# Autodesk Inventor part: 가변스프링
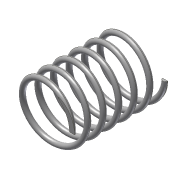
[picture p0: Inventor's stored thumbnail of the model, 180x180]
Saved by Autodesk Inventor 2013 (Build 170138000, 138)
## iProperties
Created: 2018-06
Part Number: 가변스프링
Material: 강철, 연강
Document SubType Name: Modeling
Designer: Administrator
Density: 7.86 g/cm^3
Mass: 82.8002 g
Surface Area: 106.473 cm^2
Volume: 10.5344 cm^3
Author: Administrator
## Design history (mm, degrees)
sketch "스케치1"
  geometry: L1 (0, 0)-(0, 73.25); L2 (0, 73.25)-(22.5, 73.25); C1 r 2 at (22.5, 0)
  constraints: 4 end point, 1 centre point, 1 horizontal alignment, 1 perpendicular, 1 vertical, 1 vertical alignment
  dimensions: "d0" = 73.25 distance of L1.start L1.end (derived); "d1" = 22.5 distance of L1.end L2.end; "d2" = 4 diameter of C1
feature "코일1" sketch "스케치1" pitch "d3" = 10; turns "d5" = 6; dims "d4" = 73.24999 (computed from d0), "d6" = 0, angle "d7" = 90 deg, angle "d8" = 90 deg, "d9" = 0, "d10" = 0
sketch "스케치2"
  geometry: L1 (-40, 0)-(40, 0); L2 (40, 0)-(40, 73.25); L3 (40, 73.25)-(-40, 73.25); L4 (-40, 73.25)-(-40, 0); 2 further points
  constraints: 8 end point, 2 parallel, 1 coincident, 1 horizontal, 1 horizontal alignment, 1 midpoint, 1 perpendicular
  dimensions: "d11" = 73.24999 distance of L3.end L1.start (derived); "d13" = 80 distance of L2.end L3.end
extrude "돌출1" sketch "스케치2" stored distance "d14" = 80 (= d13); taper "d15" = 0 deg
node "솔리드1"
